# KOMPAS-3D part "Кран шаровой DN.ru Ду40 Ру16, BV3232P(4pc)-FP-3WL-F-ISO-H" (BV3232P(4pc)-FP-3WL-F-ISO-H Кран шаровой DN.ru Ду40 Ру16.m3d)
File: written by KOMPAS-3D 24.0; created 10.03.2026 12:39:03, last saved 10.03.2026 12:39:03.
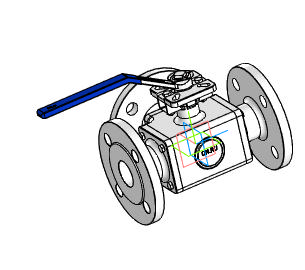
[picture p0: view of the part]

Document properties: Автор: R2D2; Полное имя файла: BV3232P(4pc)-FP-3WL-F-ISO-H Кран шаровой DN.ru Ду40 Ру16.cdw

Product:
- Part/product: Кран шаровой DN.ru Ду40 Ру16  | designation BV3232P(4pc)-FP-3WL-F-ISO-H
    Масса: 11.65
    Раздел спецификации: Прочие изделия
    Форматы листов документа: A3
    Примечание: D160-36359

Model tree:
1. Операция без истории:1

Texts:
  BV3232P(4pc)-FP-3WL-F-ISO-H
